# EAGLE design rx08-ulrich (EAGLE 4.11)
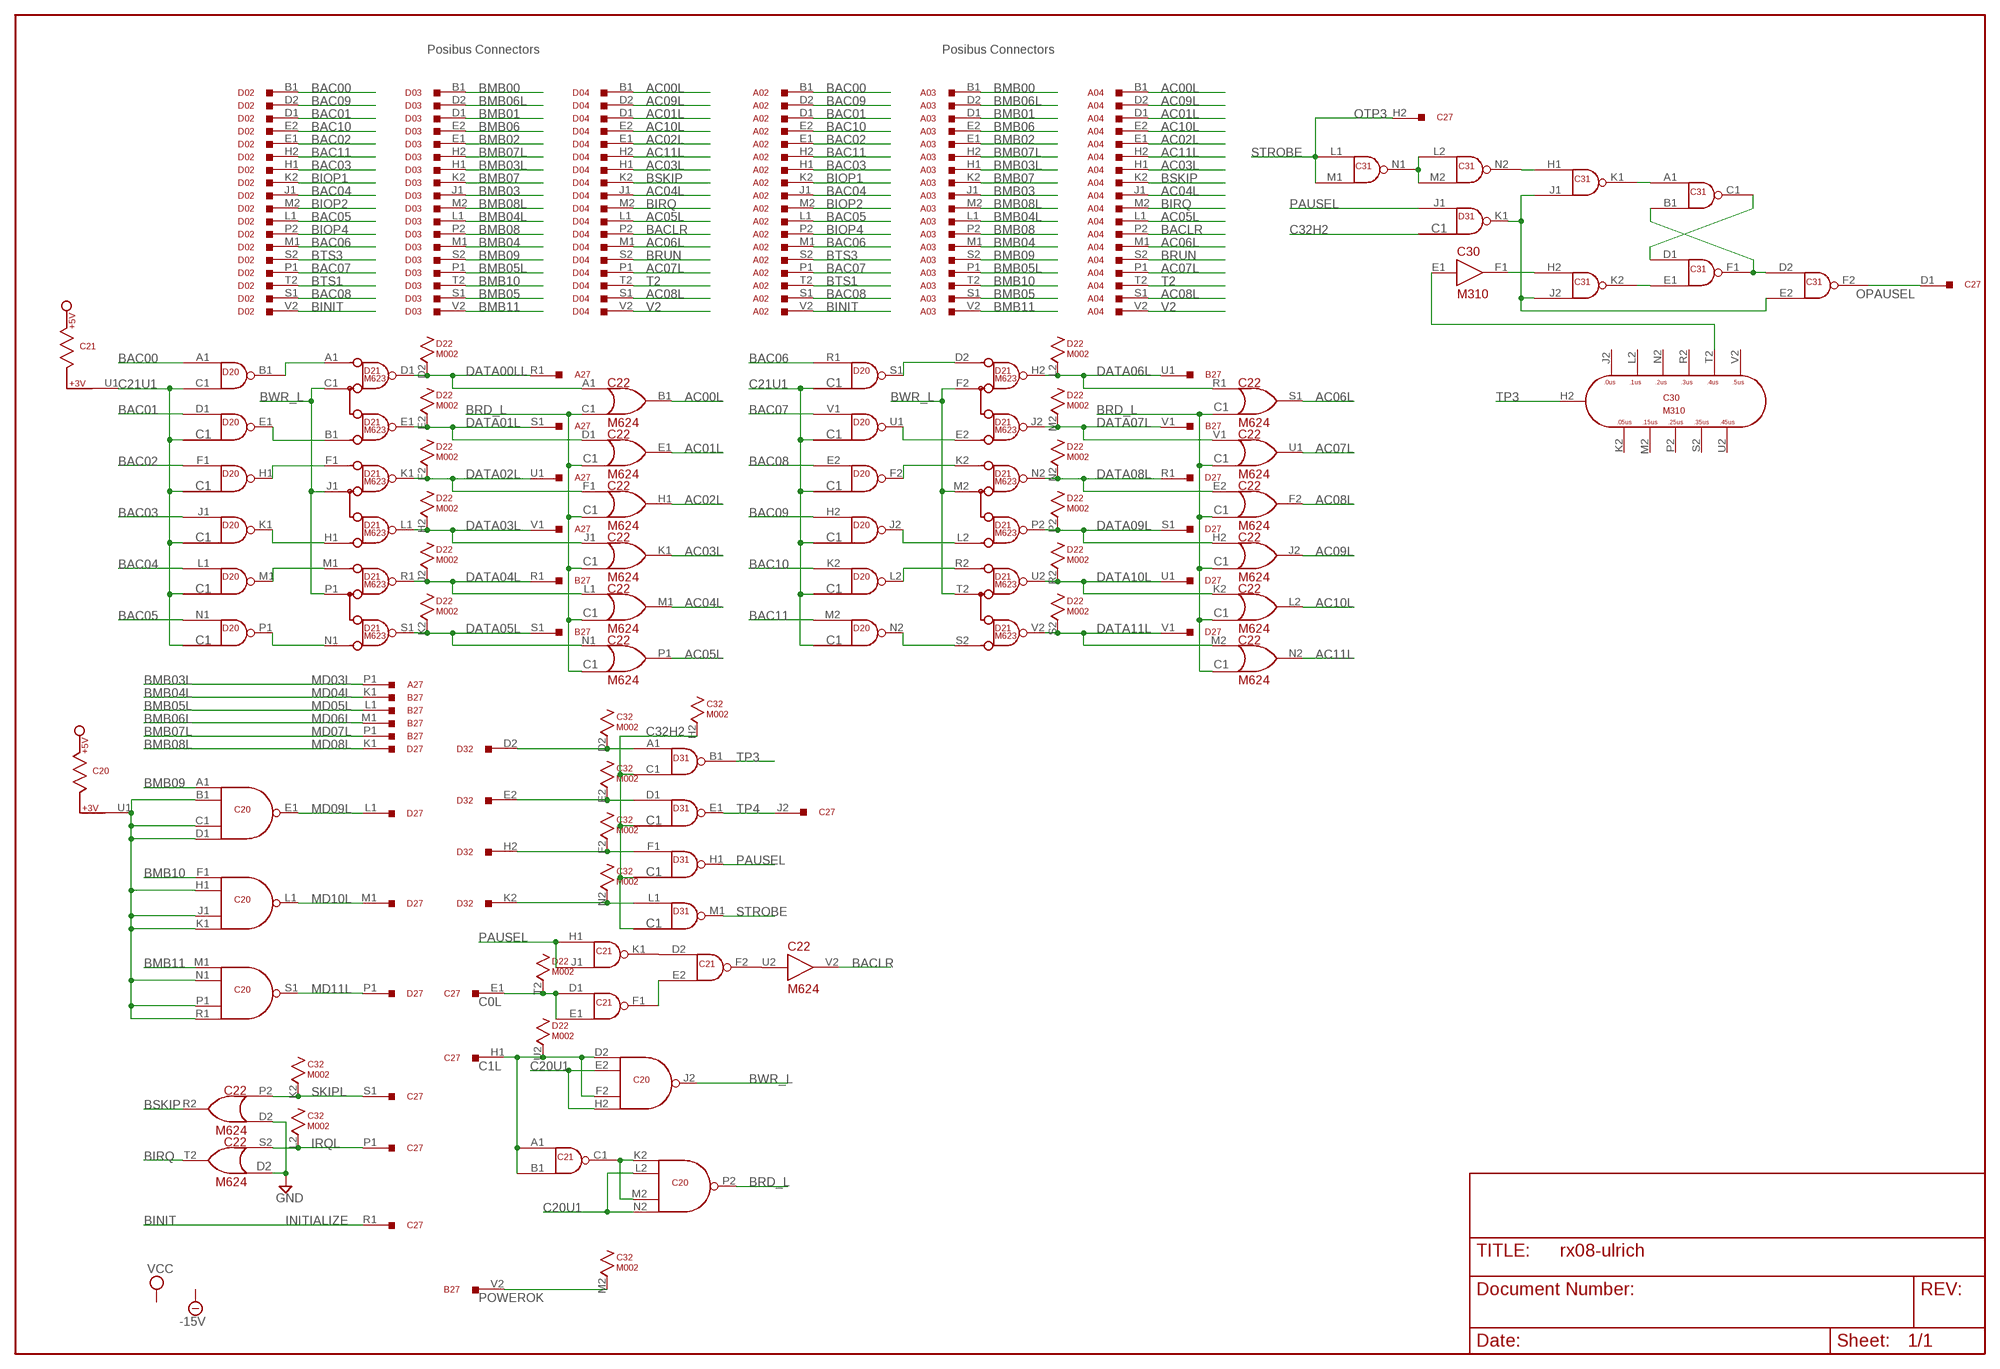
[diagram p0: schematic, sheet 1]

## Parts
A02  M903  [H807]
A03  M903  [H807]
A04  M903  [H807]
A27  M916  [H807]
B27  M916  [H807]
C20  M617  [H807]
C21  M113  [H807]
C22  M624  [H807]
C27  M916  [H807]
C30  M310  [H807]
C31  M113  [H807]
C32  M002  [H807]
D02  M903  [H807]
D03  M903  [H807]
D04  M903  [H807]
D20  M101  [H807]
D21  M623  [H807]
D22  M002  [H807]
D27  M916  [H807]
D31  M101  [H807]
D32  M903  [H807]

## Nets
AC00L: A04.B1 C22.B1(OUT) D04.B1
AC01L: A04.D1 C22.E1(OUT) D04.D1
AC02L: A04.E1 C22.H1(OUT) D04.E1
AC03L: A04.H1 C22.K1(OUT) D04.H1
AC04L: A04.J1 C22.M1(OUT) D04.J1
AC05L: A04.L1 C22.P1(OUT) D04.L1
AC06L: A04.M1 C22.S1(OUT) D04.M1
AC07L: A04.P1 C22.U1(OUT) D04.P1
AC08L: A04.S1 C22.F2(OUT) D04.S1
AC09L: A04.D2 C22.J2(OUT) D04.D2
AC10L: A04.E2 C22.L2(OUT) D04.E2
AC11L: A04.H2 C22.N2(OUT) D04.H2
BAC00: A02.B1 D02.B1 D20.A1(IN1)
BAC01: A02.D1 D02.D1 D20.D1(IN)
BAC02: A02.E1 D02.E1 D20.F1(IN)
BAC03: A02.H1 D02.H1 D20.J1(IN)
BAC04: A02.J1 D02.J1 D20.L1(IN)
BAC05: A02.L1 D02.L1 D20.N1(IN)
BAC06: A02.M1 D02.M1 D20.R1(IN)
BAC07: A02.P1 D02.P1 D20.V1(IN)
BAC08: A02.S1 D02.S1 D20.E2(IN)
BAC09: A02.D2 D02.D2 D20.H2(IN)
BAC10: A02.E2 D02.E2 D20.K2(IN)
BAC11: A02.H2 D02.H2 D20.M2(IN)
BACLR: A04.P2 C22.V2(OUT) D04.P2
BINIT: A02.V2 C27.R1 D02.V2
BIOP1: A02.K2 D02.K2
BIOP2: A02.M2 D02.M2
BIOP4: A02.P2 D02.P2
BIRQ: A04.M2 C22.T2(OUT) D04.M2
BMB00: A03.B1 D03.B1
BMB01: A03.D1 D03.D1
BMB02: A03.E1 D03.E1
BMB03: A03.J1 D03.J1
BMB03L: A03.H1 A27.P1 D03.H1
BMB04: A03.M1 D03.M1
BMB04L: A03.L1 B27.K1 D03.L1
BMB05: A03.S1 D03.S1
BMB05L: A03.P1 B27.L1 D03.P1
BMB06: A03.E2 D03.E2
BMB06L: A03.D2 B27.M1 D03.D2
BMB07: A03.K2 D03.K2
BMB07L: A03.H2 B27.P1 D03.H2
BMB08: A03.P2 D03.P2
BMB08L: A03.M2 D03.M2 D27.K1
BMB09: A03.S2 C20.A1(IN1) D03.S2
BMB10: A03.T2 C20.F1(IN1) D03.T2
BMB11: A03.V2 C20.M1(IN1) D03.V2
BRD_L: C20.P2(OUT) C22.C1(IN2)
BRUN: A04.S2 D04.S2
BSKIP: A04.K2 C22.R2(OUT) D04.K2
BTS1: A02.T2 D02.T2
BTS3: A02.S2 D02.S2
BWR_L: C20.J2(OUT) D21.C1(C) D21.F2(C) D21.J1(C) D21.M2(C) D21.P1(C) D21.T2(C)
C0L: C21.D1(IN1) C21.E1(IN2) C27.E1 D22.T2
C1L: C20.D2(IN1) C20.F2(IN3) C21.A1(IN1) C21.B1(IN2) C27.H1 D22.U2
C20U1: C20.B1(IN2) C20.C1(IN3) C20.D1(IN4) C20.E2(IN2) C20.H1(IN2) C20.H2(IN4) C20.J1(IN3) C20.K1(IN4) C20.L2(IN2) C20.N1(IN2) C20.N2(IN4) C20.P1(IN3) C20.R1(IN4) C20.U1
C21U1: C21.U1 D20.C1(IN2)
C32H2: C32.H2 D31.C1(IN2)
DATA00LL: A27.R1 C22.A1(IN1) D21.D1(D) D22.D2
DATA01L: A27.S1 C22.D1(IN) D21.E1(E) D22.E2
DATA02L: A27.U1 C22.F1(IN) D21.K1(D) D22.F2
DATA03L: A27.V1 C22.J1(IN) D21.L1(E) D22.H2
DATA04L: B27.R1 C22.L1(IN) D21.R1(D) D22.J2
DATA05L: B27.S1 C22.N1(IN) D21.S1(E) D22.K2
DATA06L: B27.U1 C22.R1(IN) D21.H2(D) D22.L2
DATA07L: B27.V1 C22.V1(IN) D21.J2(E) D22.M2
DATA08L: C22.E2(IN) D21.N2(D) D22.N2 D27.R1
DATA09L: C22.H2(IN) D21.P2(E) D22.P2 D27.S1
DATA10L: C22.K2(IN) D21.U2(D) D22.R2 D27.U1
DATA11L: C22.M2(IN) D21.V2(E) D22.S2 D27.V1
GND: C22.D2(IN2)
IRQL: C22.S2(IN) C27.P1 C32.L2
MD09L: C20.E1(OUT) D27.L1
MD10L: C20.L1(OUT) D27.M1
MD11L: C20.S1(OUT) D27.P1
N$1: D20.B1(OUT) D21.A1(A)
N$2: D20.E1(OUT) D21.B1(B)
N$3: D20.H1(OUT) D21.F1(A)
N$4: D20.K1(OUT) D21.H1(B)
N$5: D20.P1(OUT) D21.N1(B)
N$6: D20.M1(OUT) D21.M1(A)
N$7: C20.K2(IN1) C20.M2(IN3) C21.C1(OUT)
N$8: D20.N2(OUT) D21.S2(B)
N$9: C32.D2 D31.A1(IN1) D32.D2
N$10: D20.J2(OUT) D21.L2(B)
N$11: D20.U1(OUT) D21.E2(B)
N$12: D20.S1(OUT) D21.D2(A)
N$13: D20.F2(OUT) D21.K2(A)
N$14: D20.L2(OUT) D21.R2(A)
N$15: C32.E2 D31.D1(IN) D32.E2
N$16: C32.F2 D31.F1(IN) D32.H2
N$17: C32.N2 D31.L1(IN) D32.K2
N$18: C31.E2(IN2) C31.J1(IN2) C31.J2(IN2) D31.K1(OUT)
N$19: C21.E2(IN2) C21.F1(OUT)
N$20: C21.D2(IN1) C21.K1(OUT)
N$21: C31.C1(OUT) C31.D1(IN1)
N$22: C31.B1(IN2) C31.D2(IN1) C31.F1(OUT)
N$23: C21.F2(OUT) C22.U2(IN)
N$24: C30.E1(IN) C30.T2
N$25: C30.F1(OUT) C31.H2(IN1)
N$26: C31.L2(IN1) C31.M2(IN2) C31.N1(OUT)
N$28: C31.H1(IN1) C31.N2(OUT)
N$29: C31.A1(IN1) C31.K1(OUT)
N$30: C31.E1(IN2) C31.K2(OUT)
OPAUSEL: C27.D1 C31.F2(OUT)
PAUSEL: C21.H1(IN1) C21.J1(IN2) D31.H1(OUT) D31.J1(IN)
POWEROK: B27.V2 C32.M2
SKIPL: C22.P2(IN1) C27.S1 C32.K2
STROBE: C27.H2 C31.L1(IN1) C31.M1(IN2) D31.M1(OUT)
T2: A04.T2 D04.T2
TP3: C30.H2 D31.B1(OUT)
TP4: C27.J2 D31.E1(OUT)
V2: A04.V2 D04.V2
Unconnected: A27.A1 A27.A2 A27.B1 A27.B2 A27.C1 A27.C2 A27.D1 A27.D2 A27.E1 A27.E2 A27.F1 A27.F2 A27.H1 A27.H2 A27.J1 A27.J2 A27.K1 A27.K2 A27.L1 A27.L2 A27.M1 A27.M2 A27.N1 A27.N2 A27.P2 A27.R2 A27.S2 A27.T1 A27.T2 A27.U2 A27.V2 B27.A1 B27.A2 B27.B1 B27.B2 B27.C1 B27.C2 B27.D1 B27.D2 B27.E1 B27.E2 B27.F1 B27.F2 B27.H1 B27.H2 B27.J1 B27.J2 B27.K2 B27.L2 B27.M2 B27.N1 B27.N2 B27.P2 B27.R2 B27.S2 B27.T1 B27.T2 B27.U2 C20.R2(IN1) C20.S2(IN2) C20.T2(IN3) C20.U2(IN4) C20.V1 C20.V2(OUT) C21.H2(IN1) C21.J2(IN2) C21.K2(OUT) C21.L1(IN1) C21.L2(IN1) C21.M1(IN2) C21.M2(IN2) C21.N1(OUT) C21.N2(OUT) C21.P1(IN1) C21.P2(IN1) C21.R1(IN2) C21.R2(IN2) C21.S1(OUT) C21.S2(OUT) C21.T2(IN1) C21.U2(IN2) C21.V1 C21.V2(OUT) C27.A1 C27.A2 C27.B1 C27.B2 C27.C1 C27.C2 C27.D2 C27.E2 C27.F1 C27.F2 C27.J1 C27.K1 C27.K2 C27.L1 C27.L2 C27.M1 C27.M2 C27.N1 C27.N2 C27.P2 C27.R2 C27.S2 C27.T1 C27.T2 C27.U1 C27.U2 C27.V1 C27.V2 C30.H1(IN) C30.J1(OUT) C30.J2 C30.K2 C30.L2 C30.M2 C30.N2 C30.P2 C30.R2 C30.S2 C30.U2 C30.V2 C31.P1(IN1) C31.P2(IN1) C31.R1(IN2) C31.R2(IN2) C31.S1(OUT) C31.S2(OUT) C31.T2(IN1) C31.U1 C31.U2(IN2) C31.V1 C31.V2(OUT) C32.J2 C32.P2 C32.R2 C32.S2 C32.T2 C32.U2 C32.V2 D20.P2(IN) D20.R2(OUT) D20.S2(IN) D20.T2(OUT) D20.U2(IN) D20.V2(OUT) D22.V2 D27.A1 D27.A2 D27.B1 D27.B2 D27.C1 D27.C2 D27.D1 D27.D2 D27.E1 D27.E2 D27.F1 D27.F2 D27.H1 D27.H2 D27.J1 D27.J2 D27.K2 D27.L2 D27.M2 D27.N1 D27.N2 D27.P2 D27.R2 D27.S2 D27.T1 D27.T2 D27.U2 D27.V2 D31.E2(IN) D31.F2(OUT) D31.H2(IN) D31.J2(OUT) D31.K2(IN) D31.L2(OUT) D31.M2(IN) D31.N1(IN) D31.N2(OUT) D31.P1(OUT) D31.P2(IN) D31.R1(IN) D31.R2(OUT) D31.S1(OUT) D31.S2(IN) D31.T2(OUT) D31.U1(OUT) D31.U2(IN) D31.V1(IN) D31.V2(OUT) D32.B1 D32.D1 D32.E1 D32.H1 D32.J1 D32.L1 D32.M1 D32.M2 D32.P1 D32.P2 D32.S1 D32.S2 D32.T2 D32.V2

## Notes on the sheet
- Posibus Connectors | Posibus Connectors
- OTP3
- MD03L
- MD04L
- MD05L
- MD06L
- MD07L
- MD08L
- INITIALIZE

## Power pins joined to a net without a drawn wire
-15V: C32.B2(-15V) D22.B2(-15V)
GND: A02.A1 A02.C1 A02.C2 A02.F1 A02.F2 A02.J2 A02.K1 A02.L2 A02.N1 A02.N2 A02.R1 A02.R2 A02.T1 A02.U2 A03.A1 A03.C1 A03.C2 A03.F1 A03.F2 A03.J2 A03.K1 A03.L2 A03.N1 A03.N2 A03.R1 A03.R2 A03.T1 A03.U2 A04.A1 A04.C1 A04.C2 A04.F1 A04.F2 A04.J2 A04.K1 A04.L2 A04.N1 A04.N2 A04.R1 A04.R2 A04.T1 A04.U2 C20.C2(GND) C20.T1(GND) C21.C2(GND) C21.T1(GND) C22.C2(GND) C22.T1(GND) C30.C2(GND) C30.T1(GND) C31.C2(GND) C31.T1(GND) C32.C2(GND) D02.A1 D02.C1 D02.C2 D02.F1 D02.F2 D02.J2 D02.K1 D02.L2 D02.N1 D02.N2 D02.R1 D02.R2 D02.T1 D02.U2 D03.A1 D03.C1 D03.C2 D03.F1 D03.F2 D03.J2 D03.K1 D03.L2 D03.N1 D03.N2 D03.R1 D03.R2 D03.T1 D03.U2 D04.A1 D04.C1 D04.C2 D04.F1 D04.F2 D04.J2 D04.K1 D04.L2 D04.N1 D04.N2 D04.R1 D04.R2 D04.T1 D04.U2 D20.C2(GND) D20.T1(GND) D21.C2(GND) D21.T1(GND) D21.U1(GND) D21.V1(GND) D22.C2(GND) D31.C2(GND) D31.T1(GND) D32.A1 D32.C1 D32.C2 D32.F1 D32.F2 D32.J2 D32.K1 D32.L2 D32.N1 D32.N2 D32.R1 D32.R2 D32.T1 D32.U2
VCC: C20.A2(VCC) C21.A2(VCC) C22.A2(VCC) C30.A2(VCC) C31.A2(VCC) C32.A2(VCC) D20.A2(VCC) D21.A2(VCC) D22.A2(VCC) D31.A2(VCC)

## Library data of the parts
A02-A04 D02-D04 D32 = dec-m:M903: Two-sided Posibus cable/connector.
A27 B27 C27 D27 = dec-m:M916: Simple 36 pin connector/wire cable
C20 = dec-m:M617: 6 4-input NAND Buffers
C21 C31 = dec-m:M113: 10 2-input NAND Gates
C22 = dec-m:M624: Bus Data Interface The M101 contains 15 two-input NAND gates. One input of each gate is tied to a common line so that all data signals can be enabled simultaneously. Each data signal presents one TTL load. The common input presents 15 loads. Each output can drive 10 loads. Power: 5V@82ma (max.)
C30 = dec-m:M310: Tapped Delay Line
C32 D22 = dec-m:M002: 15 Clamped Loads
D20 D31 = dec-m:M101: Bus Data Interface The M101 contains 15 two-input NAND gates. One input of each gate is tied to a common line so that all data signals can be enabled simultaneously. Each data signal presents one TTL load. The common input presents 15 loads. Each output can drive 10 loads. Power: 5V@82ma (max.)
D21 = dec-m:M623: 6 Dual Bus Drivers

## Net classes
1 Supply: width 1.905 mm, drill 0.508 mm

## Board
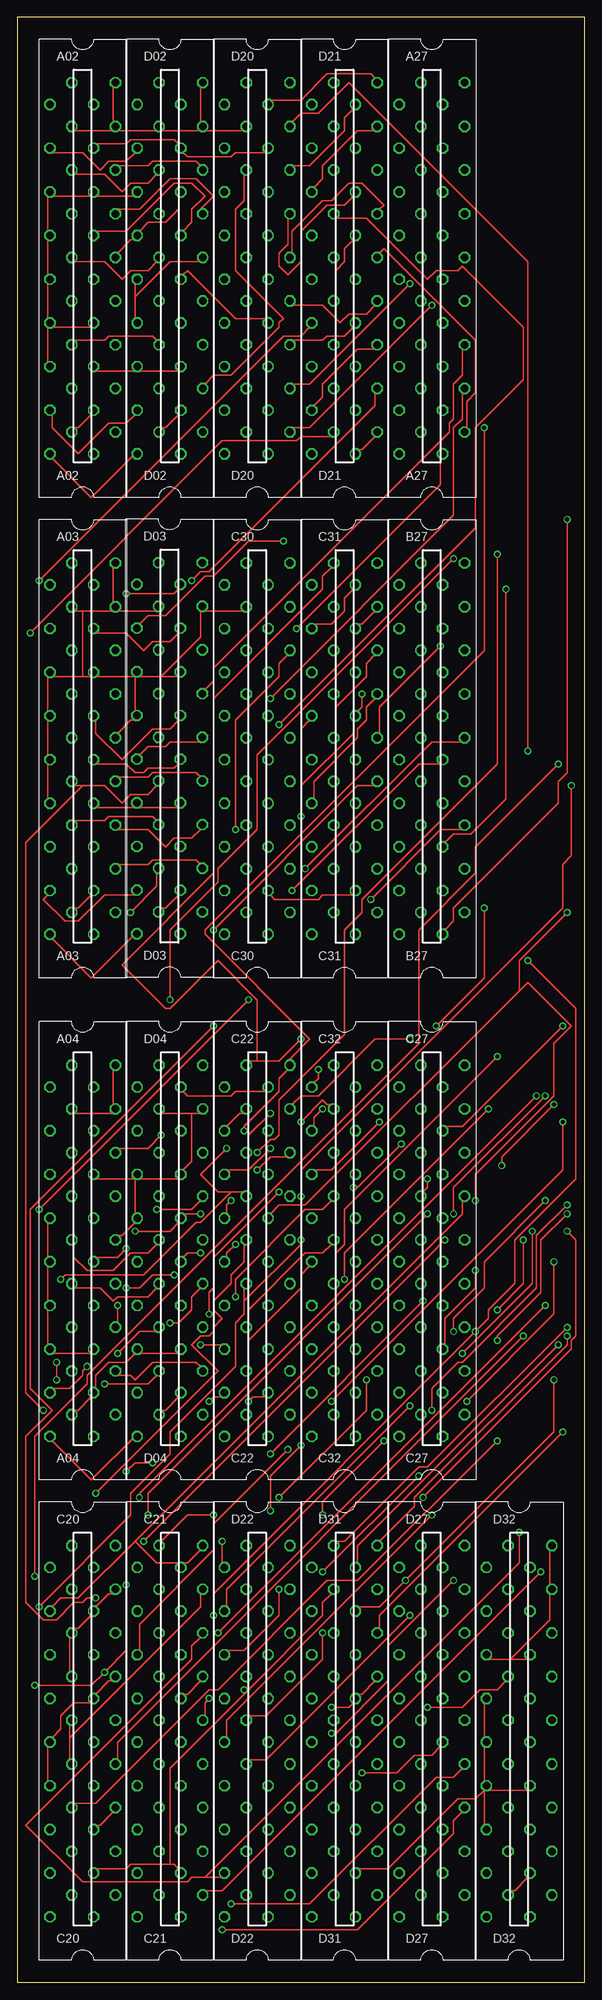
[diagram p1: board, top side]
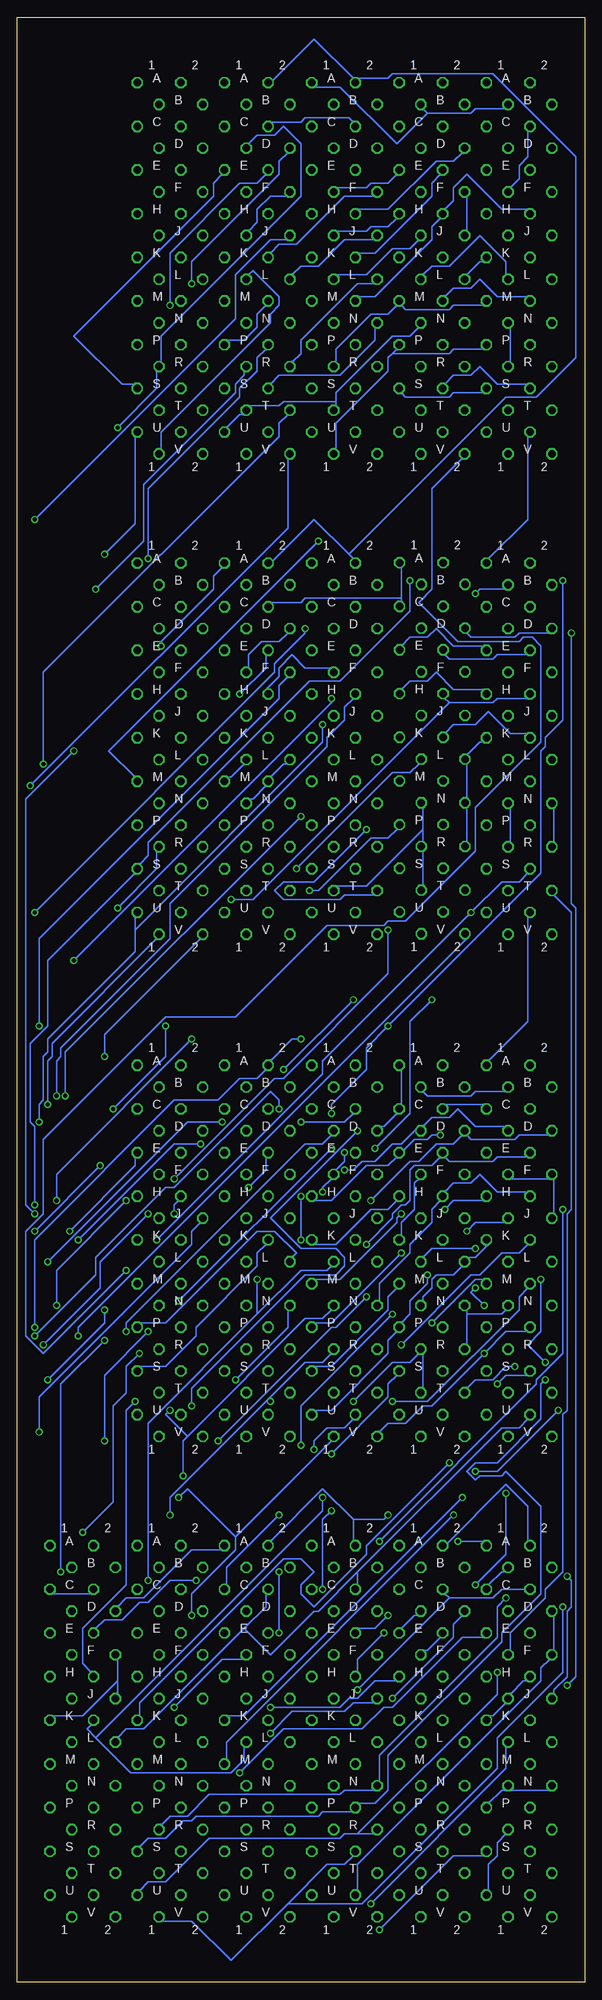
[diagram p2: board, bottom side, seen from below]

Size 82.55 x 285.75 mm. Coordinates in mm from the lower left corner, seen from the top.
Outline: 0,0 82.55,0 82.55,285.75 0,285.75 0,0
Copper layers (1*16): Top 0.035mm / dielectric 1.5mm / Bottom 0.035mm
Design rules "olimex10mil": minimum track width 10mil, minimum drill 24mil, track to track 10mil, track to pad 10mil, pad to pad 10mil, via to via 10mil, smd to smd 10mil, copper to edge 40mil, drill to drill 10mil, minimum pad ring 10mil, minimum via ring 8mil, stop-mask expansion 0mil, vias tented up to drill 0mil, thermal gap 10mil

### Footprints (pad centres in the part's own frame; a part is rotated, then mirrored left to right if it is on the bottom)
H807 = drill 1.092 octagon: A1 4.763,28.575; A2 -1.587,28.575; B1 1.587,25.4; B2 -4.763,25.4; C1 4.763,22.225; C2 -1.587,22.225; D1 1.587,19.05; D2 -4.763,19.05; E1 4.763,15.875; E2 -1.587,15.875; F1 1.587,12.7; F2 -4.763,12.7; H1 4.763,9.525; H2 -1.587,9.525; J1 1.587,6.35; J2 -4.763,6.35; K1 4.763,3.175; K2 -1.587,3.175; L1 1.587,0; L2 -4.763,0; M1 4.763,-3.175; M2 -1.587,-3.175; N1 1.587,-6.35; N2 -4.763,-6.35; P1 4.763,-9.525; P2 -1.587,-9.525; R1 1.587,-12.7; R2 -4.763,-12.7; S1 4.763,-15.875; S2 -1.587,-15.875; T1 1.587,-19.05; T2 -4.763,-19.05; U1 4.763,-22.225; U2 -1.587,-22.225; V1 1.587,-25.4; V2 -4.763,-25.4

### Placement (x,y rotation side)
A02  9.53,247.65 0 top
A03  9.53,177.8 0 top
A04  9.53,104.78 0 top
A27  60.33,247.65 0 top
B27  60.33,177.8 0 top
C20  9.53,34.92 0 top
C21  22.23,34.92 0 top
C22  34.92,104.78 0 top
C27  60.33,104.78 0 top
C30  34.92,177.8 0 top
C31  47.62,177.8 0 top
C32  47.62,104.78 0 top
D02  22.23,247.65 0 top
D03  22.16,177.86 0 top
D04  22.23,104.78 0 top
D20  34.92,247.65 0 top
D21  47.62,247.65 0 top
D22  34.92,34.92 0 top
D27  60.33,34.92 0 top
D31  47.62,34.92 0 top
D32  73.03,34.92 0 top

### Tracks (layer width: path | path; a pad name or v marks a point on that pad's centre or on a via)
-15V  (via drill 0.61)
  Top 0.254: v29.84,64.14 29.84,60.96 D22.B2 | v3.17,112.39 v33.66,142.88 | v43.81,132.72 43.81,131.44 43.18,130.81 C32.B2
  Bottom 0.254: v29.84,64.14 6.99,87 6.99,87.63 3.17,91.44 v3.17,112.39 | v33.66,142.88 v43.81,132.72
AC00L
  Top 0.254: C22.B1 36.2,129.54 31.75,129.54 31.11,128.91 24.77,128.91 24.13,129.54 D04.B1
  Bottom 0.254: A04.B1 11.43,129.54 15.88,129.54 16.51,128.91 22.86,128.91 23.5,129.54 D04.B1
AC01L  (via drill 0.61)
  Top 0.254: v34.92,118.11 36.83,120.02 39.37,120.02 C22.E1
  Bottom 0.254: A04.D1 11.43,124.46 15.88,124.46 18.41,127 19.68,125.73 22.23,125.73 23.5,124.46 D04.D1 24.13,124.46 26.67,121.92 27.94,121.92 30.48,119.38 32.38,119.38 33.66,118.11 v34.92,118.11
AC02L  (via drill 0.61)
  Top 0.254: v20.95,123.19 19.05,121.28 14.61,121.28 A04.E1
  Bottom 0.254: v20.95,123.19 22.23,123.19 22.86,122.56 24.77,122.56 26.67,120.65 D04.E1 27.3,120.02 28.57,118.75 31.75,118.75 36.83,113.67 39.37,113.67 C22.H1
AC03L  (via drill 0.61)
  Top 0.254: v20.32,112.39 25.4,112.39 26.67,113.67 D04.H1
  Bottom 0.254: v20.32,112.39 19.05,113.67 14.61,113.67 A04.H1 | C22.K1 39.37,107.31 36.2,107.31 31.11,112.39 28.57,112.39 27.3,113.67 D04.H1
AC04L  (via drill 0.61)
  Top 0.254: v17.14,109.22 22.23,109.22 23.5,110.49 D04.J1 24.13,111.76 v26.67,111.76
  Bottom 0.254: v17.14,109.22 15.88,110.49 11.43,110.49 A04.J1 | v26.67,111.76 27.3,111.12 27.3,110.49 35.56,102.23 39.37,102.23 C22.M1
AC05L  (via drill 0.61)
  Top 0.254: v15.88,106.68 14.61,105.41 11.43,105.41 A04.L1 | v26.67,106.05 24.77,106.05 24.13,105.41 D04.L1
  Bottom 0.254: v15.88,106.68 22.23,106.68 23.5,105.41 D04.L1 | v26.67,106.05 36.83,95.89 39.37,95.89 C22.P1
AC06L  (via drill 0.61)
  Top 0.254: v22.23,95.89 23.5,95.89 25.4,97.79 25.4,99.69 26.67,100.97 D04.M1
  Bottom 0.254: v22.23,95.89 15.88,102.23 14.61,102.23 A04.M1 | C22.S1 39.37,89.53 36.83,89.53 28.57,97.79 28.57,99.69 27.3,100.97 D04.M1
AC07L  (via drill 0.61)
  Top 0.254: v14.61,98.42 14.61,95.89 A04.P1 | v15.88,100.97 17.78,100.97 19.68,102.87 v22.86,102.87
  Bottom 0.254: v14.61,98.42 16.51,100.33 v15.88,100.97 | v22.86,102.87 22.86,101.6 25.4,99.06 25.4,97.16 26.67,95.89 D04.P1 27.3,94.61 28.57,93.34 28.57,91.44 36.83,83.19 39.37,83.19 C22.U1
AC08L  (via drill 0.61)
  Top 0.254: A04.S1 14.61,88.27 16.51,88.27 17.14,87.63 19.68,90.17 26.04,90.17 26.67,89.53 D04.S1 | v36.83,121.28 33.66,118.11 30.48,118.11 C22.F2 | v36.83,76.83 v59.05,99.06
  Bottom 0.254: v59.05,99.06 v36.83,121.28 | v36.83,76.83 28.57,85.09 28.57,87 27.3,88.27 D04.S1
AC09L  (via drill 0.61)
  Top 0.254: v31.11,113.67 30.48,113.03 30.48,111.76 C22.J2
  Bottom 0.254: A04.D2 5.08,123.19 9.53,123.19 10.16,122.56 16.51,122.56 17.14,123.19 D04.D2 17.78,123.19 19.05,121.92 21.59,121.92 24.13,119.38 25.4,119.38 v31.11,113.67
AC10L  (via drill 0.61)
  Top 0.254: v31.75,107.31 30.48,106.05 30.48,105.41 C22.L2
  Bottom 0.254: A04.E2 8.26,120.02 12.7,120.02 13.34,119.38 19.68,119.38 20.32,120.02 D04.E2 20.95,120.02 22.23,118.75 24.77,118.75 25.4,118.11 25.4,113.67 26.04,113.03 26.67,113.03 27.94,111.76 27.94,111.12 v31.75,107.31
AC11L
  Bottom 0.254: A04.H2 8.26,114.94 12.7,114.94 15.24,117.47 16.51,116.2 19.05,116.2 20.32,114.94 D04.H2 20.95,113.67 22.23,112.39 22.23,110.49 25.4,107.31 25.4,106.05 29.84,101.6 29.84,99.06 C22.N2
BAC00
  Bottom 0.254: 22.86,271.78 16.51,271.78 15.88,272.42 11.43,272.42 A02.B1 | 22.86,271.78 23.5,272.42 D02.B1 | 22.86,271.78 27.3,267.33 35.56,275.59 39.37,275.59 D20.A1
BAC01
  Top 0.254: A02.D1 11.43,267.33 15.88,267.33 16.51,267.97 22.86,267.97 23.5,267.33 D02.D1 24.13,266.06 24.77,265.43 31.11,265.43 31.75,266.06 36.2,266.06 D20.D1
BAC02
  Top 0.254: A02.E1 14.61,264.16 19.05,264.16 19.68,264.8 26.04,264.8 26.67,264.16 D02.E1
  Bottom 0.254: D20.F1 36.2,260.99 31.75,260.99 31.11,261.62 28.57,261.62 27.3,262.89 D02.E1
BAC03
  Top 0.254: A02.H1 14.61,257.81 17.78,257.81 22.23,262.25 26.04,262.25 28.57,259.71 26.67,257.81 D02.H1
  Bottom 0.254: D20.J1 36.2,254.63 31.75,254.63 31.11,255.27 28.57,255.27 27.3,256.54 D02.H1
BAC04
  Top 0.254: A02.J1 11.43,254.63 15.88,254.63 22.86,261.62 25.4,261.62 27.3,259.71 25.4,257.81 25.4,255.91 24.13,254.63 D02.J1
  Bottom 0.254: D20.L1 36.2,248.28 31.75,248.28 27.94,252.09 25.4,252.09 24.13,253.37 D02.J1
BAC05
  Top 0.254: D20.N1 36.2,241.94 31.75,241.94 24.77,248.92 24.13,248.28 D02.L1
  Bottom 0.254: A02.L1 11.43,248.28 11.43,250.19 15.24,254 19.68,249.56 22.23,249.56 23.5,248.28 D02.L1
BAC06
  Bottom 0.254: A02.M1 14.61,243.84 19.05,243.84 19.68,243.21 26.04,243.21 26.67,243.84 D02.M1 27.3,243.84 28.57,242.57 31.11,242.57 36.2,237.49 36.2,235.59 D20.R1
BAC07
  Bottom 0.254: 27.94,236.85 27.3,237.49 D02.P1 | 27.94,236.85 28.57,236.22 28.57,234.31 36.2,226.69 36.2,222.88 D20.V1 | 27.94,236.85 19.68,236.85 19.05,237.49 14.61,237.49 A02.P1
BAC08
  Top 0.254: D20.E2 33.02,262.89 33.02,259.08 31.75,257.81 31.75,248.92 38.73,241.94 38.1,241.3 38.1,240.66 31.11,233.68 28.57,233.68 27.3,232.41 D02.S1
  Bottom 0.254: A02.S1 14.61,231.14 19.05,231.14 19.68,230.5 26.04,230.5 26.67,231.14 D02.S1
BAC09
  Top 0.254: A02.D2 5.08,266.06 9.53,266.06 12.06,263.52 13.34,264.8 15.88,264.8 17.14,266.06 D02.D2
  Bottom 0.254: D20.H2 33.02,257.81 28.57,257.81 21.59,264.8 19.05,264.8 17.78,266.06 D02.D2
BAC10
  Top 0.254: A02.E2 8.26,262.89 12.7,262.89 15.24,260.35 16.51,261.62 19.05,261.62 20.32,262.89 D02.E2
  Bottom 0.254: D20.K2 33.02,251.46 30.48,251.46 22.23,259.71 22.23,261.62 20.95,262.89 D02.E2
BAC11
  Bottom 0.254: A02.H2 8.26,257.81 12.06,257.81 17.14,262.89 19.05,260.99 19.05,259.08 20.32,257.81 D02.H2 20.95,256.54 22.23,255.27 22.23,253.37 30.48,245.11 33.02,245.11 D20.M2
BACLR  (via drill 0.61)
  Top 0.254: v14.61,91.44 17.78,94.61 20.32,94.61 D04.P2
  Bottom 0.254: A04.P2 8.26,94.61 11.43,94.61 v14.61,91.44 22.23,83.82 23.5,83.82 26.04,81.28 28.57,81.28 29.84,80.01 C22.V2
BINIT  (via drill 0.61)
  Top 0.254: v66.67,103.5 66.67,100.97 62.23,96.52 62.23,92.71 C27.R1 | A02.V2 5.08,221.62 10.79,215.9 17.14,222.25 D02.V2
  Bottom 0.254: v66.67,103.5 78.74,91.44 81.28,93.98 81.28,109.22 78.74,111.76 78.74,122.56 60.96,140.34 50.8,140.34 37.47,153.67 29.21,153.67 28.57,154.31 26.04,154.31 15.88,164.47 15.88,170.81 6.35,180.34 6.35,194.31 7.62,195.58 8.89,195.58 9.53,194.94 18.41,194.94 24.13,200.66 22.23,202.56 22.23,217.17 17.78,221.62 D02.V2
BIOP1
  Top 0.254: A02.K2 8.26,250.19 12.7,250.19 15.24,247.65 16.51,248.92 19.05,248.92 20.32,250.19 D02.K2
BIOP2
  Bottom 0.254: A02.M2 8.26,245.11 12.7,245.11 15.24,247.65 16.51,246.38 19.05,246.38 20.32,245.11 D02.M2
BIOP4
  Top 0.254: A02.P2 8.26,238.76 12.7,238.76 13.34,239.4 19.68,239.4 20.32,238.76 D02.P2
BIRQ  (via drill 0.61)
  Top 0.254: A04.M2 8.26,100.97 12.06,100.97 13.97,99.06 14.61,99.69 19.05,99.69 20.32,100.97 D04.M2 | v27.94,84.45 28.57,85.09 29.84,85.09 C22.T2
  Bottom 0.254: v27.94,84.45 22.86,84.45 9.53,97.79 9.53,99.69 8.26,100.97 A04.M2
BMB00  (via drill 0.61)
  Top 0.254: v15.88,201.93 22.86,201.93 23.5,202.56 D03.B1
  Bottom 0.254: v15.88,201.93 15.24,202.56 11.43,202.56 A03.B1
BMB01
  Top 0.254: A03.D1 11.43,196.22 15.88,196.22 18.41,193.68 19.68,194.94 22.23,194.94 23.5,196.22 D03.D1
BMB02
  Bottom 0.254: A03.E1 14.61,194.31 19.05,194.31 21.59,196.85 22.86,195.58 25.4,195.58 26.67,194.31 D03.E1
BMB03
  Top 0.254: A03.J1 11.43,183.51 11.43,181.61 15.24,177.8 19.68,182.25 22.23,182.25 23.5,183.51 D03.J1
BMB03L
  Top 0.254: A27.P1 64.77,237.49 64.77,233.68 63.5,232.41 63.5,227.33 62.87,226.69 62.87,225.43 28.57,191.13 28.57,189.23 27.3,187.96 D03.H1
  Bottom 0.254: A03.H1 14.61,187.96 19.05,187.96 21.59,190.5 22.86,189.23 25.4,189.23 26.67,187.96 D03.H1
BMB04
  Top 0.254: A03.M1 14.61,175.26 19.05,175.26 19.68,175.9 26.04,175.9 26.67,175.26 D03.M1
BMB04L  (via drill 0.61)
  Top 0.254: A03.L1 11.43,177.16 15.88,177.16 17.14,175.9 18.41,175.9 19.05,176.53 22.86,176.53 23.5,177.16 D03.L1 | v41.91,161.93 60.33,180.34 64.77,180.34 B27.K1
  Bottom 0.254: v41.91,161.93 27.94,175.9 25.4,175.9 24.13,177.16 D03.L1
BMB05
  Top 0.254: A03.S1 14.61,162.56 19.05,162.56 19.68,163.19 26.04,163.19 26.67,162.56 D03.S1
BMB05L  (via drill 0.61)
  Top 0.254: A03.P1 14.61,167.64 19.05,167.64 21.59,165.1 22.86,166.37 25.4,166.37 26.67,167.64 D03.P1 | v40.01,158.75 58.42,177.16 61.59,177.16 B27.L1
  Bottom 0.254: v40.01,158.75 38.73,158.75 31.11,166.37 28.57,166.37 27.3,167.64 D03.P1
BMB06
  Bottom 0.254: A03.E2 8.26,193.04 12.7,193.04 13.34,192.41 19.68,192.41 20.32,193.04 D03.E2
BMB06L  (via drill 0.61)
  Top 0.254: v38.73,209.55 33.66,209.55 28.57,204.47 27.3,204.47 21.59,198.75 19.05,198.75 17.78,197.49 D03.D2
  Bottom 0.254: A03.D2 5.08,196.22 9.53,196.22 10.16,195.58 16.51,195.58 17.14,196.22 D03.D2 | v38.73,209.55 69.22,179.07 65.41,175.26 B27.M1
BMB07
  Bottom 0.254: A03.K2 8.26,181.61 10.79,181.61 13.97,184.78 15.88,182.88 19.05,182.88 20.32,181.61 D03.K2
BMB07L  (via drill 0.61)
  Top 0.254: v51.44,157.48 61.59,167.64 64.77,167.64 B27.P1
  Bottom 0.254: 19.68,186.06 13.34,186.06 12.7,186.69 8.26,186.69 A03.H2 | 19.68,186.06 20.32,186.69 D03.H2 | v51.44,157.48 48.26,157.48 19.68,186.06
BMB08
  Top 0.254: A03.P2 8.26,168.91 12.7,168.91 13.34,169.54 19.68,169.54 20.32,168.91 D03.P2
BMB08L  (via drill 0.61)
  Top 0.254: 9.53,173.99 12.7,173.99 15.24,171.45 16.51,172.72 19.05,172.72 20.32,173.99 D03.M2 | 9.53,173.99 8.26,173.99 A03.M2 | v19.68,75.56 17.14,75.56 v15.88,74.3 | v3.81,83.19 1.27,85.72 1.27,165.74 9.53,173.99
  Bottom 0.254: v19.68,75.56 31.75,63.5 31.75,62.23 39.37,54.61 41.27,56.52 41.27,57.78 39.37,59.69 41.27,61.59 43.81,61.59 64.77,40.64 64.77,38.73 D27.K1 | v15.88,74.3 12.7,74.3 v3.81,83.19
BMB09  (via drill 0.61)
  Top 0.254: v18.41,64.14 v62.23,107.95 | v16.51,155.57 20.32,159.38 20.32,161.29 D03.S2
  Bottom 0.254: v18.41,64.14 14.61,64.14 C20.A1 | v62.23,107.95 38.1,132.08 38.1,133.99 v16.51,155.57 12.06,160.02 9.53,160.02 8.26,161.29 A03.S2
BMB10
  Top 0.254: D03.T2 17.14,158.12 12.7,158.12 8.89,154.31 6.99,154.31 3.81,157.48 4.45,158.12 A03.T2
  Bottom 0.254: C20.F1 10.79,48.26 10.79,50.8 5.71,55.88 5.71,57.15 3.17,59.69 3.17,82.55 2.54,83.19 2.54,111.76 1.91,112.39 1.91,155.57 4.45,158.12 A03.T2
BMB11  (via drill 0.61)
  Top 0.254: v73.66,93.98 14.61,34.92 14.61,32.38 C20.M1 | A03.V2 5.08,151.76 10.79,146.05 17.14,152.4 D03.V2
  Bottom 0.254: v73.66,93.98 73.66,95.25 17.14,151.76 D03.V2
BRD_L  (via drill 0.61)
  Top 0.254: v69.85,78.74 49.53,58.42 45.09,58.42 29.21,42.55 27.94,42.55 11.43,26.04 8.26,26.04 C20.P2 | v63.5,94.61 63.5,96.52 67.94,100.97 67.94,104.78 v76.83,113.67 | v57.15,137.16 52.07,137.16 43.81,128.91 41.27,128.91 40.01,127.64 C22.C1
  Bottom 0.254: v69.85,78.74 69.85,88.27 v63.5,94.61 | v76.83,113.67 76.83,117.47 v57.15,137.16
BRUN  (via drill 0.61)
  Top 0.254: v12.7,87 19.05,87 20.32,88.27 D04.S2
  Bottom 0.254: v12.7,87 11.43,88.27 8.26,88.27 A04.S2
BSKIP  (via drill 0.61)
  Top 0.254: A04.K2 8.26,107.31 8.26,105.41 10.16,103.5 13.97,103.5 16.51,106.05 19.05,106.05 20.32,107.31 D04.K2 | v26.67,92.71 29.84,92.71 C22.R2
  Bottom 0.254: v26.67,92.71 16.51,102.87 15.24,102.87 12.06,106.05 9.53,106.05 8.26,107.31 A04.K2
BTS1
  Top 0.254: A02.T2 5.08,227.97 5.08,226.06 8.89,222.25 13.34,226.69 15.88,226.69 17.14,227.97 D02.T2
BTS3
  Bottom 0.254: A02.S2 8.26,232.41 12.7,232.41 15.24,234.95 16.51,233.68 19.05,233.68 20.32,232.41 D02.S2
BWR_L  (via drill 0.61)
  Top 0.254: D21.C1 52.07,269.24 49.53,269.24 44.45,264.16 44.45,262.25 43.18,260.99 D21.F2 | D21.M2 46.35,245.11 46.35,248.92 47.62,250.19 47.62,252.09 48.9,253.37 D21.J1 | v2.54,59.05 2.54,79.38 10.16,87 10.16,88.27 58.42,136.53 58.42,153.03 66.67,161.29 66.67,165.1 v78.74,177.16 | D21.P1 52.07,237.49 49.53,237.49 44.45,232.41 44.45,230.5 43.18,229.24 D21.T2
  Bottom 0.254: D21.P1 52.07,238.76 49.53,238.76 47.62,240.66 47.62,242.57 46.35,243.84 D21.M2 | D21.F2 43.18,259.71 45.72,259.71 47.62,257.81 47.62,255.91 48.9,254.63 D21.J1 | v2.54,59.05 1.91,58.42 1.91,54.61 2.54,53.98 2.54,44.45 4.45,42.55 4.45,41.91 C20.J2 | v78.74,177.16 78.74,190.5 44.45,224.79 44.45,226.69 43.18,227.97 D21.T2
C0L  (via drill 0.61)
  Top 0.254: 27.3,15.24 25.4,15.24 24.77,14.61 9.53,14.61 1.27,22.86 25.4,46.99 25.4,48.9 26.67,50.16 C21.E1 | 27.3,15.24 29.84,15.24 D22.T2 | v74.93,109.22 74.93,101.6 v64.77,91.44 | v73.03,65.41 73.03,60.96 27.3,15.24
  Bottom 0.254: C21.D1 24.13,53.34 24.77,53.34 26.67,51.44 C21.E1 | v74.93,109.22 65.41,118.75 65.41,120.02 C27.E1 | v64.77,91.44 66.67,89.53 66.67,85.72 68.58,83.82 68.58,69.85 v73.03,65.41
C1L
  Top 0.254: C21.A1 26.67,62.87 24.77,60.96 24.13,60.96 C21.B1 23.5,60.96 20.32,60.96 17.14,64.14 | 17.14,64.14 8.89,55.88 6.35,55.88 5.08,54.61 C20.D2 | 17.14,64.14 64.77,111.76 64.77,113.67 C27.H1
  Bottom 0.254: C20.D2 4.45,53.34 4.45,48.26 C20.F2 5.08,46.99 6.35,45.72 6.35,43.81 33.02,17.14 33.02,13.34 D22.U2
C20U1
  Top 0.254: C20.H1 13.97,43.81 13.34,43.81 11.43,41.91 C20.J1 10.79,40.64 8.26,40.64 6.35,38.73 6.35,36.83 5.08,35.56 C20.L2 4.45,34.29 4.45,29.21 C20.N2 | C20.C1 13.97,56.52 13.34,56.52 11.43,54.61 C20.D1 10.79,53.34 8.89,51.44 8.26,51.44 C20.E2 7.62,50.16 7.62,45.09 C20.H2 | C20.R1 11.43,22.86 12.06,22.86 13.97,24.77 C20.P1
  Bottom 0.254: C20.H2 8.26,43.81 8.89,43.81 10.79,41.91 C20.J1 11.43,40.64 13.34,38.73 13.97,38.73 C20.K1 | C20.B1 11.43,59.69 12.06,59.69 13.97,57.78 C20.C1 | C20.U1 13.97,13.34 13.97,17.14 12.7,18.41 12.7,20.32 11.43,21.59 C20.R1 | C20.P1 13.97,26.04 12.06,27.94 11.43,27.94 C20.N1 10.79,27.94 5.08,27.94 C20.N2
C21U1  (via drill 0.61)
  Top 0.254: v76.2,59.69 29.84,13.34 27.3,13.34 C21.U1 | v69.85,93.34 69.85,93.98 76.2,100.33 76.2,107.95 v80.01,111.76 | v74.3,179.07 74.3,250.19 48.26,276.23 43.81,271.78 41.27,271.78 40.01,270.51 D20.C1
  Bottom 0.254: v76.2,59.69 76.2,87 v69.85,93.34 | v80.01,111.76 81.28,113.03 81.28,172.09 v74.3,179.07
C32H2  (via drill 0.61)
  Top 0.254: v44.45,67.94 44.45,69.85 v53.34,78.74 | v31.75,99.69 31.75,102.23 41.91,112.39 44.45,112.39 45.72,113.67 C32.H2
  Bottom 0.254: v44.45,67.94 52.07,60.33 52.07,57.78 D31.C1 | v53.34,78.74 36.83,95.25 36.2,95.25 v31.75,99.69
DATA00LL  (via drill 0.61)
  Top 0.254: v57.15,83.82 30.48,57.15 30.48,54.61 D22.D2 | v33.02,123.83 33.02,124.46 38.1,129.54 38.1,131.44 39.37,132.72 C22.A1 39.37,133.99 42.55,137.16 27.3,152.4 27.3,153.03 67.94,193.68 v67.94,226.06
  Bottom 0.254: D21.D1 48.9,267.33 47.62,268.61 45.09,268.61 43.81,269.88 41.27,267.33 41.27,259.71 61.59,239.4 61.59,235.59 A27.R1 62.23,234.31 62.23,231.78 v67.94,226.06 | v57.15,83.82 57.15,86.36 40.64,102.87 36.2,102.87 34.92,104.14 34.92,105.41 36.2,106.68 41.27,106.68 45.72,111.12 v33.02,123.83
DATA01L  (via drill 0.61)
  Top 0.254: v28.57,53.34 28.57,56.52 v66.67,94.61 68.58,96.52 68.58,97.79 72.39,101.6 72.39,107.95 81.28,116.84 81.28,141.6 v74.3,148.59 | v36.83,186.69 63.5,213.36 63.5,226.06 64.77,227.33 64.77,231.14 A27.S1
  Bottom 0.254: A27.S1 65.41,232.41 67.31,232.41 74.3,239.4 53.98,259.71 53.98,261.62 52.7,262.89 D21.E1 | v28.57,53.34 30.48,51.44 33.02,51.44 D22.E2 | v66.67,94.61 66.67,95.89 40.64,121.92 38.1,121.92 36.83,123.19 C22.D1 | v36.83,186.69 36.83,186.06 v74.3,148.59
DATA02L  (via drill 0.61)
  Top 0.254: A27.U1 65.41,226.06 65.41,229.87 66.67,231.14 66.67,238.76 53.34,252.09 52.7,251.46 D21.K1 | v38.1,57.15 38.1,53.34 33.02,48.26 30.48,48.26 D22.F2 | v36.83,68.58 36.83,73.66 v41.27,78.11 | v27.94,97.16 27.94,100.33 28.57,100.97 28.57,105.41 v38.1,114.94 | v69.85,207.65 69.85,177.16 50.16,157.48 50.16,155.57 47.62,153.03 47.62,137.79 38.1,128.27 38.1,123.19 37.47,122.56 36.83,122.56 v34.92,120.65
  Bottom 0.254: v38.1,57.15 38.1,67.31 v36.83,68.58 | v41.27,78.11 41.27,83.82 v27.94,97.16 | v38.1,114.94 38.1,115.57 36.83,116.84 C22.F1 36.2,118.11 34.92,119.38 v34.92,120.65 | v69.85,207.65 65.41,212.09 65.41,224.79 A27.U1
DATA03L  (via drill 0.61)
  Top 0.254: v76.83,98.42 v29.21,50.8 | v66.67,113.67 66.67,117.47 78.11,128.91 78.11,136.53 80.64,139.06 74.3,145.41 73.03,144.15 | 73.03,144.15 41.91,113.03 38.1,113.03 36.83,111.76 C22.J1 | v40.64,196.85 61.59,217.81 61.59,221.62 A27.V1 | v80.01,155.57 73.03,148.59 73.03,144.15
  Bottom 0.254: A27.V1 61.59,222.88 61.59,225.43 45.72,241.3 45.72,242.57 44.45,243.84 44.45,245.11 48.26,248.92 48.9,248.28 D21.L1 | v29.21,50.8 33.02,46.99 33.02,45.09 D22.H2 | v76.83,98.42 76.83,103.5 v66.67,113.67 | v40.64,196.85 40.64,196.22 45.09,191.77 45.09,190.5 v80.01,155.57
DATA04L  (via drill 0.61)
  Top 0.254: v71.12,202.56 71.12,172.09 66.04,167 63.5,167 62.23,165.74 B27.R1 | v45.72,36.2 46.35,36.2 53.98,43.81 53.98,48.9 v63.5,58.42 | v67.94,156.21 67.94,146.05 v60.96,139.06 | v68.58,127 47.62,106.05 v47.62,102.23
  Bottom 0.254: v71.12,202.56 64.14,209.55 64.14,217.81 50.8,231.14 50.8,232.41 49.53,233.68 49.53,234.31 D21.R1 | v45.72,36.2 42.55,39.37 34.92,39.37 33.66,40.64 30.48,40.64 D22.J2 | v63.5,58.42 63.5,81.28 47.62,97.16 | 47.62,97.16 41.27,103.5 37.47,103.5 36.83,104.14 C22.L1 | v67.94,156.21 62.23,161.93 62.23,164.47 B27.R1 | v60.96,139.06 60.96,134.62 v68.58,127 | v47.62,102.23 47.62,97.16
DATA05L  (via drill 0.61)
  Top 0.254: v44.45,50.8 44.45,46.99 36.2,38.73 33.66,38.73 D22.K2 | v58.42,73.66 v44.45,59.69 | v25.4,203.84 26.67,205.1 27.94,205.1 52.07,229.24 52.07,231.14 D21.S1 | v60.33,83.19 60.33,86.36 64.14,90.17 64.77,90.17 75.56,100.97 75.56,108.58 v80.01,113.03
  Bottom 0.254: v44.45,59.69 v44.45,50.8 | v58.42,73.66 58.42,78.74 57.78,79.38 | 57.78,79.38 40.64,96.52 38.1,96.52 36.83,97.79 C22.N1 | v25.4,203.84 25.4,199.39 35.56,189.23 40.01,189.23 63.5,165.74 63.5,163.83 64.77,162.56 B27.S1 65.41,161.29 78.11,148.59 78.11,139.06 80.64,136.53 80.64,125.09 80.01,124.46 v80.01,113.03 | 57.78,79.38 60.96,82.55 v60.33,83.19
DATA06L  (via drill 0.61)
  Top 0.254: v60.33,67.94 30.48,38.1 30.48,35.56 D22.L2 | v79.38,125.09 79.38,118.11 v45.72,84.45 | v38.1,182.88 66.67,211.46 66.67,226.06 73.66,233.04 73.66,240.66 64.77,249.56 64.14,248.92 60.96,248.92 59.69,247.65 50.8,256.54 46.35,256.54 D21.H2
  Bottom 0.254: v60.33,67.94 60.33,70.48 45.72,85.09 | 45.72,85.09 40.64,90.17 38.1,90.17 36.83,91.44 C22.R1 | 65.41,153.03 65.41,149.86 78.11,137.16 78.11,135.25 78.74,134.62 78.74,128.27 79.38,127.64 v79.38,125.09 | 65.41,153.03 65.41,154.94 B27.U1 | v45.72,84.45 45.72,85.09 | v38.1,182.88 38.1,180.34 65.41,153.03
DATA07L  (via drill 0.61)
  Top 0.254: v57.15,53.34 36.2,32.38 33.66,32.38 D22.M2 | v80.01,212.72 80.01,175.9 78.74,174.62 78.74,171.45 63.5,156.21 63.5,154.31 62.23,153.03 B27.V1 | v59.05,70.48 80.64,92.08 80.64,93.34 81.28,93.98 81.28,107.95 v80.01,109.22 | v70.48,118.75 70.48,120.02 v78.11,127.64
  Bottom 0.254: v57.15,53.34 57.15,56.52 50.8,62.87 50.8,64.77 | 50.8,64.77 36.83,78.74 C22.V1 | v80.01,212.72 50.8,241.94 50.8,248.28 45.72,253.37 43.18,253.37 D21.J2 | 50.8,64.77 57.78,71.75 v59.05,70.48 | v70.48,118.75 v80.01,109.22 | v78.11,127.64 78.11,133.99 77.47,134.62 77.47,136.53 62.23,151.76 B27.V1
DATA08L  (via drill 0.61)
  Top 0.254: v36.83,126.36 33.66,123.19 33.66,121.28 C22.E2 | v3.17,203.84 38.73,239.4 41.27,239.4 42.55,240.66 D21.N2 | v11.43,55.88 10.16,55.88 9.53,55.24 8.26,55.24 5.71,52.7 3.81,52.7 1.27,55.24 1.27,79.38 5.08,83.19 1.91,86.36 1.91,112.39 v28.57,139.06
  Bottom 0.254: D27.R1 61.59,22.86 60.33,24.13 57.78,24.13 54.61,27.3 35.56,27.3 34.92,27.94 30.48,27.94 D22.N2 29.84,29.21 29.84,33.02 12.7,50.16 12.7,54.61 v11.43,55.88 | v36.83,126.36 36.83,127.64 31.75,132.72 31.75,135.89 v28.57,139.06 6.35,161.29 6.35,179.07 5.71,179.71 5.71,180.97 3.17,183.51 v3.17,203.84
DATA09L  (via drill 0.61)
  Top 0.254: 31.11,114.94 29.21,114.94 26.67,117.47 v30.48,121.28 | 31.11,114.94 33.02,114.94 C22.H2 | v22.23,142.88 22.23,153.03 29.21,160.02 29.21,161.93 34.92,167.64 34.92,178.44 v63.5,207.01 | v5.71,90.17 v5.71,87.63 | v6.35,102.23 6.99,102.87 18.41,102.87 26.04,110.49 26.67,110.49 31.11,114.94
  Bottom 0.254: D27.S1 64.77,19.68 63.5,20.95 60.96,20.95 58.42,23.5 57.15,23.5 56.52,24.13 38.73,24.13 38.1,24.77 33.66,24.77 D22.P2 33.02,26.04 30.48,26.04 28.57,27.94 28.57,33.02 12.06,49.53 12.06,50.8 6.35,56.52 6.35,69.22 11.43,74.3 12.06,73.66 15.24,73.66 15.88,73.03 17.14,74.3 15.88,75.56 12.7,75.56 6.35,81.92 6.35,87 v5.71,87.63 | v30.48,121.28 25.4,126.36 25.4,139.7 v22.23,142.88 | v63.5,207.01 63.5,217.17 50.16,230.5 50.16,231.78 47.62,234.31 47.62,236.22 46.35,237.49 D21.P2 | v5.71,90.17 8.26,92.71 6.35,94.61 v6.35,102.23
DATA10L  (via drill 0.61)
  Top 0.254: v11.43,71.12 29.21,88.9 25.4,92.71 26.67,93.98 27.94,93.98 28.57,94.61 28.57,95.25 29.84,96.52 28.57,97.79 28.57,99.06 31.11,101.6 31.11,102.87 33.02,104.78 33.02,107.31 C22.K2 | v15.88,57.78 15.88,48.26 v12.7,45.09 10.79,43.18 v2.54,43.18 | v1.91,196.22 29.84,224.16 40.64,224.16 41.27,224.79 45.72,224.79 D21.U2
  Bottom 0.254: 33.02,21.59 34.92,21.59 35.56,20.95 54.61,20.95 60.96,14.61 63.5,14.61 64.77,13.34 D27.U1 | 33.02,21.59 30.48,21.59 D22.R2 | v11.43,71.12 11.43,62.23 v15.88,57.78 | v12.7,45.09 12.7,41.91 33.02,21.59 | v1.91,196.22 1.91,156.84 1.27,156.21 1.27,44.45 v2.54,43.18
DATA11L  (via drill 0.61)
  Top 0.254: 33.02,99.06 33.02,97.16 31.75,95.89 31.75,89.53 22.23,80.01 22.23,76.83 16.51,71.12 16.51,67.94 v3.17,54.61 | 33.02,99.06 33.02,100.97 C22.M2 | v80.64,173.99 80.64,163.83 79.38,162.56 79.38,156.21 41.27,118.11 v41.27,114.3 | v41.27,107.95 41.27,107.31 33.02,99.06
  Bottom 0.254: 43.18,11.43 37.47,17.14 34.92,17.14 33.66,18.41 D22.S2 | 43.18,11.43 51.44,3.17 57.15,8.89 61.59,8.89 D27.V1 | v3.17,54.61 3.17,45.09 12.7,35.56 12.7,31.11 32.38,11.43 43.18,11.43 | v80.64,173.99 43.18,211.46 43.18,221.62 D21.V2 | v41.27,114.3 v41.27,107.95
GND  (via drill 0.61)
  Top 0.254: D32.U2 71.75,13.34 72.39,13.34 74.3,15.24 D32.T1 74.3,16.51 74.3,21.59 D32.R1 74.3,22.86 74.3,27.94 | 67.94,27.94 66.67,26.67 64.14,26.67 53.98,16.51 49.53,16.51 D31.T1 | 67.94,27.94 67.94,22.86 D32.R2 | D32.N2 67.94,27.94 | 74.3,27.94 68.58,27.94 D32.N2 | 74.3,27.94 D32.N1 | D32.A1 77.47,62.87 77.47,57.78 D32.C1 77.47,56.52 77.47,52.7 71.75,46.99 | 22.23,17.14 22.86,17.14 23.5,16.51 C21.T1 | 22.23,17.14 16.51,17.14 15.88,16.51 11.43,16.51 C20.T1 | D32.J2 67.94,40.64 67.94,35.56 D32.L2 67.94,34.29 67.94,29.21 D32.N2 | 71.75,46.99 68.58,46.99 D32.F2 | 71.75,46.99 74.3,46.99 D32.F1 | 33.66,42.55 v33.02,42.55 | 33.66,42.55 44.45,53.34 44.45,55.24 45.72,56.52 D31.C2 | 22.23,17.14 22.23,31.11 33.66,42.55 | A02.U2 8.26,226.06 8.89,226.06 10.79,227.97 A02.T1 10.79,229.24 10.79,234.31 A02.R1 11.43,234.31 17.14,234.31 D02.R2 17.78,234.31 23.5,234.31 | D21.V1 49.53,222.88 50.16,222.88 52.07,224.79 D21.U1 | D02.U2 20.95,226.06 21.59,226.06 23.5,227.97 D02.T1 23.5,229.24 23.5,234.31 | D02.N1 23.5,240.66 23.5,235.59 D02.R1 23.5,234.31 | A02.C2 8.26,269.24 13.97,269.24 A02.C1 | A02.C1 14.61,269.24 20.32,269.24 D02.C2 20.95,269.24 26.67,269.24 D02.C1 | A02.A1 13.97,275.59 13.97,270.51 A02.C1 | D02.C1 26.67,270.51 26.67,275.59 D02.A1 | D20.C2 33.02,269.24 27.3,269.24 D02.C1 | A02.R2 4.45,235.59 4.45,240.66 A02.N2 | A02.N2 4.45,241.94 4.45,247.01 A02.L2 4.45,248.28 4.45,253.37 A02.J2 4.45,254.63 4.45,259.71 A02.F2 5.08,259.71 10.79,259.71 A02.F1 11.43,259.71 17.14,259.71 D02.F2 | 17.14,245.11 17.14,247.01 D02.L2 | 17.14,245.11 17.14,241.94 D02.N2 | A02.K1 14.61,251.46 16.51,253.37 17.14,253.37 D02.J2 17.78,254.63 19.05,255.91 21.59,255.91 23.5,257.81 23.5,259.71 D02.F1
  Top 0.254: 17.14,245.11 22.23,250.19 26.67,250.19 D02.K1 | A02.N1 10.79,240.66 5.08,240.66 A02.N2 | 9.53,199.39 13.97,199.39 A03.C1 | 9.53,199.39 8.26,199.39 A03.C2 | D03.C2 20.32,199.39 14.61,199.39 A03.C1 | A03.A1 13.97,205.74 13.97,200.66 A03.C1 | A03.N2 4.45,172.09 4.45,177.16 A03.L2 4.45,178.44 4.45,183.51 A03.J2 4.45,184.78 4.45,189.87 A03.F2 5.08,189.87 9.53,189.87 | 9.53,189.87 10.79,189.87 A03.F1 11.43,189.87 17.14,189.87 | 9.53,199.39 9.53,189.87 | D03.U2 20.95,156.21 21.59,156.21 23.5,158.12 D03.T1 | C31.T1 48.9,158.12 44.45,158.12 43.81,157.48 37.47,157.48 36.83,158.12 C30.T1 | C30.C2 33.02,199.39 27.3,199.39 D03.C1 26.67,199.39 26.67,195.58 20.95,189.87 | A03.U2 8.26,156.21 8.89,156.21 10.79,158.12 A03.T1 10.79,159.38 10.79,164.47 A03.R1 | A03.K1 14.61,181.61 16.51,183.51 17.14,183.51 D03.J2 17.14,184.78 17.14,189.87 | 20.95,189.87 17.78,189.87 D03.F2 17.14,189.87 | 20.95,189.87 23.5,189.87 D03.F1 | D03.K1 26.67,180.34 22.23,180.34 21.59,179.71 19.05,179.71 17.78,178.44 D03.L2 | A03.N1 11.43,170.81 17.14,170.81 D03.N2 17.78,170.81 23.5,170.81 D03.N1 | A04.U2 8.26,83.19 8.89,83.19 10.79,85.09 A04.T1 11.43,86.36 11.43,88.27 13.34,90.17 15.88,90.17 17.14,91.44 D04.R2 17.78,91.44 23.5,91.44 D04.R1 | A04.C2 8.26,126.36 13.97,126.36 A04.C1 13.97,127.64 13.97,132.72 A04.A1 | 25.4,126.36 26.67,126.36 D04.C1 | 25.4,126.36 20.95,126.36 D04.C2 | C22.C2 33.02,126.36 32.38,126.36 30.48,124.46 C22.D2 | v41.27,125.09 44.45,128.27 45.09,127.64 45.72,127.64 C32.C2 | D04.U2 20.95,83.19 21.59,83.19 23.5,85.09 D04.T1 | v33.66,84.45 34.29,85.09 36.2,85.09 C22.T1 | A04.N1 10.79,97.79 10.79,92.71 A04.R1 10.79,91.44 5.08,91.44 A04.R2 4.45,92.71 4.45,97.79 A04.N2 4.45,99.06 4.45,104.14 A04.L2 4.45,105.41 4.45,110.49 A04.J2
  Top 0.254: A04.K1 14.61,108.58 15.24,108.58 17.14,110.49 D04.J2 17.14,111.76 17.14,116.84 | 17.14,116.84 11.43,116.84 A04.F1 | 17.14,116.84 D04.F2 17.78,116.84 23.5,116.84 D04.F1 24.13,118.11 25.4,119.38 25.4,126.36
  Bottom 0.254: D32.C2 71.75,56.52 77.47,56.52 D32.C1 | 19.68,55.88 13.34,55.88 12.06,57.15 C20.C2 | 19.68,55.88 20.32,56.52 C21.C2 | 49.53,51.44 64.14,36.83 66.67,36.83 67.94,35.56 D32.L2 | 49.53,51.44 46.35,54.61 46.35,56.52 D31.C2 | 67.94,43.81 67.94,41.91 D32.J2 | 67.94,43.81 67.94,46.99 D32.F2 | 67.94,43.81 73.03,38.73 77.47,38.73 D32.K1 | v33.02,42.55 19.68,55.88 | A02.N1 10.79,240.66 10.79,235.59 A02.R1 | D21.U1 52.07,226.06 50.16,227.97 49.53,227.97 D21.T1 48.9,229.24 44.45,229.24 43.81,229.87 36.2,229.87 | 36.2,229.87 36.2,231.14 27.94,239.4 25.4,239.4 24.13,240.66 D02.N1 | 36.2,229.87 36.2,229.24 D20.T1 | D21.C2 45.72,270.51 41.27,270.51 40.64,271.14 34.29,271.14 33.66,270.51 D20.C2 | A02.K1 14.61,250.19 15.24,250.19 17.14,248.28 D02.L2 | D02.F2 17.14,259.71 17.14,254.63 D02.J2 | A02.C2 8.26,269.24 8.26,265.43 9.53,264.16 9.53,262.25 10.79,260.99 A02.F1 | A03.R2 4.45,165.74 4.45,170.81 A03.N2 | D03.T1 23.5,159.38 23.5,164.47 D03.R1 23.5,165.74 23.5,167.64 | 23.5,167.64 23.5,170.81 D03.N1 | 23.5,167.64 31.75,159.38 36.2,159.38 C30.T1 | 26.67,201.29 26.67,205.74 D03.A1 | 26.67,201.29 26.67,200.66 D03.C1 | 26.67,201.29 40.64,201.29 41.27,200.66 45.72,200.66 C31.C2 | A03.N1 10.79,170.81 10.79,165.74 A03.R1 | D03.R2 17.14,165.74 17.14,170.81 D03.N2 17.14,172.09 17.14,177.16 D03.L2 17.14,178.44 15.24,180.34 14.61,180.34 A03.K1 | 33.02,59.69 33.02,57.78 D22.C2 | 33.02,59.69 12.06,80.64 9.53,80.64 8.26,81.92 A04.U2 | C22.D2 29.84,124.46 29.21,124.46 27.3,126.36 D04.C1 26.67,127.64 26.67,132.72 D04.A1 | v41.27,125.09 34.92,125.09 33.66,126.36 C22.C2 | A04.C1 14.61,127.64 20.32,127.64 D04.C2
  Bottom 0.254: 17.14,97.16 17.14,97.79 D04.N2 | 17.14,97.16 17.14,92.71 D04.R2 | D04.T1 23.5,86.36 23.5,91.44 D04.R1 24.13,91.44 25.4,90.17 27.94,90.17 v33.66,84.45 | A04.J2 4.45,111.76 4.45,116.84 A04.F2 5.08,116.84 10.79,116.84 A04.F1 | A04.K1 13.97,107.31 15.88,105.41 17.14,105.41 D04.L2 17.78,104.14 19.05,102.87 21.59,102.87 22.23,102.23 22.23,100.97 23.5,99.69 23.5,99.06 D04.N1 | D04.K1 26.67,108.58 26.67,110.49 24.77,112.39 24.77,116.2 24.13,116.84 D04.F1 | 17.14,97.16 12.06,97.16 11.43,97.79 A04.N1 | A03.U2 8.26,154.94 8.26,139.7 13.97,133.99 A04.A1 | A02.U2 8.26,224.79 8.26,212.72 13.97,207.01 A03.A1 | 49.53,51.44 45.72,47.62 39.37,53.98 38.73,53.98 33.02,59.69
IRQL
  Top 0.254: C22.S2 33.66,89.53 33.66,93.34 41.27,100.97 41.27,102.87 42.55,104.14 C32.L2
  Bottom 0.254: C27.P1 64.77,95.89 60.96,95.89 47.62,109.22 45.09,109.22 41.91,106.05 42.55,105.41 C32.L2
MD09L  (via drill 0.61)
  Top 0.254: v50.16,30.48 55.24,30.48 57.78,33.02 60.33,33.02 61.59,34.29 D27.L1
  Bottom 0.254: v50.16,30.48 43.81,36.83 32.38,36.83 29.21,40.01 27.94,40.01 17.78,50.16 14.61,50.16 C20.E1
MD10L  (via drill 0.61)
  Top 0.254: v31.11,11.43 42.55,11.43 60.96,29.84 63.5,29.84 64.77,31.11 D27.M1
  Bottom 0.254: v31.11,11.43 11.43,31.11 11.43,34.29 C20.L1
MD11L  (via drill 0.61)
  Top 0.254: v29.84,7.62 49.53,7.62 63.5,21.59 63.5,23.5 64.77,24.77 D27.P1
  Bottom 0.254: v29.84,7.62 19.05,18.41 14.61,18.41 C20.S1
N$1
  Top 0.254: D20.B1 36.83,273.69 41.27,273.69 45.09,277.5 51.44,277.5 52.07,276.86 D21.A1
N$2
  Top 0.254: D20.E1 40.01,264.16 42.55,264.16 47.62,269.24 47.62,271.14 48.9,272.42 D21.B1
N$3
  Top 0.254: D20.H1 39.37,256.54 39.37,252.73 38.1,251.46 38.1,249.56 39.37,248.28 41.27,250.19 41.27,254.63 45.09,258.44 47.62,258.44 48.9,259.71 D21.F1
N$4
  Top 0.254: D20.K1 40.01,251.46 40.01,254.63 44.45,259.08 45.72,259.08 48.26,261.62 50.16,261.62 53.34,258.44 52.7,257.81 D21.H1
N$5
  Top 0.254: D20.P1 40.01,238.76 44.45,238.76 45.09,239.4 47.62,239.4 48.9,240.66 D21.N1
N$6
  Top 0.254: D20.M1 40.01,243.84 44.45,243.84 46.99,241.3 48.26,242.57 50.8,242.57 52.07,243.84 D21.M1
N$7
  Top 0.254: 7.62,35.56 7.62,37.47 C20.K2 | 7.62,35.56 7.62,32.38 C20.M2 | 7.62,35.56 26.67,54.61 26.67,56.52 C21.C1
N$8
  Bottom 0.254: D20.N2 30.48,240.66 30.48,238.76 35.56,233.68 44.45,233.68 45.72,232.41 D21.S2
N$9  (via drill 0.61)
  Top 0.254: v44.45,127 43.18,125.73 43.18,124.46 C32.D2 | v80.01,93.98 80.01,92.71 57.78,70.48 57.78,69.22 52.7,64.14 D31.A1
  Bottom 0.254: D31.A1 52.7,62.87 57.15,62.87 64.14,55.88 66.67,55.88 67.94,54.61 D32.D2 | v44.45,127 44.45,128.27 45.72,129.54 59.69,115.57 60.96,115.57 71.12,105.41 71.12,102.87 v80.01,93.98
N$10
  Bottom 0.254: D20.J2 30.48,253.37 34.92,253.37 38.73,249.56 41.27,249.56 42.55,248.28 D21.L2
N$11  (via drill 0.61)
  Top 0.254: v60.33,243.84 42.55,226.06 40.01,226.06 D20.U1
  Bottom 0.254: v60.33,243.84 60.33,251.46 50.16,261.62 47.62,261.62 46.35,262.89 D21.E2
N$12  (via drill 0.61)
  Top 0.254: v57.15,247.01 42.55,232.41 40.01,232.41 D20.S1
  Bottom 0.254: v57.15,247.01 57.15,250.19 44.45,262.89 44.45,264.8 43.18,266.06 D21.D2
N$13
  Bottom 0.254: D20.F2 30.48,259.71 34.92,259.71 41.91,252.73 44.45,252.73 45.72,251.46 D21.K2
N$14
  Bottom 0.254: D20.L2 30.48,247.01 33.02,247.01 41.27,238.76 41.27,236.85 42.55,235.59 D21.R2
N$15  (via drill 0.61)
  Top 0.254: D31.D1 49.53,54.61 52.7,54.61 v56.52,58.42 78.11,80.01 v78.11,87.63 | v48.9,115.57 49.53,115.57 v55.88,121.92 | v73.66,107.95 73.66,101.6 v69.85,97.79
  Bottom 0.254: v56.52,58.42 60.33,58.42 63.5,55.24 64.77,55.24 67.31,52.7 69.85,52.7 71.12,51.44 D32.E2 | v48.9,115.57 46.35,118.11 46.35,120.02 C32.E2 | v55.88,121.92 59.69,121.92 v73.66,107.95 | v69.85,97.79 69.85,95.89 v78.11,87.63
N$16  (via drill 0.61)
  Top 0.254: v59.69,40.01 64.77,40.01 67.31,42.55 69.85,42.55 71.12,43.81 D32.H2 | v52.7,125.09 45.72,118.11 43.18,118.11 C32.F2 | v78.11,104.78 78.11,97.16 v65.41,84.45
  Bottom 0.254: v59.69,40.01 52.7,46.99 49.53,46.99 D31.F1 | v52.7,125.09 57.78,125.09 v78.11,104.78 | v65.41,84.45 66.67,83.19 66.67,57.78 73.03,51.44 73.03,46.35 71.75,45.09 D32.H2
N$17  (via drill 0.61)
  Top 0.254: v50.8,87.63 50.8,83.19 v38.1,70.48
  Bottom 0.254: 71.12,35.56 72.39,36.83 71.75,37.47 D32.K2 | 71.12,35.56 66.04,30.48 51.44,30.48 49.53,32.38 49.53,34.29 D31.L1 | v50.8,87.63 43.18,95.25 43.18,97.79 C32.N2 | v38.1,70.48 38.1,68.58 71.12,35.56
N$18  (via drill 0.61)
  Top 0.254: v17.78,70.48 17.78,71.12 v75.56,128.91 | 41.27,173.99 41.27,182.25 42.55,183.51 C31.J2 | v41.27,169.54 41.27,173.99 | 41.27,173.99 48.9,181.61 48.9,183.51 C31.J1 49.53,184.78 50.16,185.42 v50.16,187.32
  Bottom 0.254: v17.78,70.48 49.53,38.73 52.07,38.73 D31.K1 | v75.56,128.91 75.56,135.25 v41.27,169.54 | v50.16,187.32 46.35,191.13 46.35,193.04 C31.E2
N$19
  Bottom 0.254: C21.F1 23.5,48.26 22.86,48.26 20.95,50.16 C21.E2
N$20  (via drill 0.61)
  Top 0.254: v27.94,41.27 27.3,40.64 27.3,38.73 C21.K1
  Bottom 0.254: v27.94,41.27 19.05,50.16 19.05,52.07 17.78,53.34 C21.D2
N$21
  Top 0.254: C31.D1 49.53,197.49 50.16,197.49 52.07,199.39 C31.C1
N$22
  Top 0.254: C31.D2 43.18,197.49 45.72,197.49 47.62,199.39 47.62,201.29 48.9,202.56 C31.B1
  Bottom 0.254: C31.F1 48.9,191.13 48.9,193.04 46.99,194.94 44.45,194.94 43.18,196.22 C31.D2
N$23  (via drill 0.61)
  Top 0.254: v39.37,77.47 28.57,66.67 28.57,62.87 17.78,52.07 17.78,48.26 C21.F2
  Bottom 0.254: v39.37,77.47 39.37,78.74 37.47,80.64 34.92,80.64 33.66,81.92 C22.U2
N$24  (via drill 0.61)
  Top 0.254: v31.75,167.64 31.75,183.51 38.1,189.87 38.1,191.77 39.37,193.04 C30.E1
  Bottom 0.254: v31.75,167.64 39.37,160.02 43.81,160.02 45.09,158.75 43.81,157.48 35.56,157.48 34.92,158.12 30.48,158.12 C30.T2
N$25
  Bottom 0.254: C30.F1 36.83,191.13 40.64,191.13 42.55,193.04 44.45,191.13 44.45,189.87 46.35,187.96 C31.H2
N$26
  Bottom 0.254: C31.L2 43.18,177.16 43.81,177.16 45.72,175.26 C31.M2 46.35,173.99 48.26,172.09 48.9,172.09 C31.N1
N$28
  Top 0.254: C31.N2 43.18,172.09 43.18,174.62 49.53,180.97 49.53,182.25 50.8,183.51 50.8,185.42 52.07,186.69 C31.H1
N$29  (via drill 0.61)
  Top 0.254: v61.59,194.31 52.7,185.42 52.7,181.61 C31.K1
  Bottom 0.254: v61.59,194.31 61.59,194.94 53.98,202.56 53.98,204.47 52.7,205.74 C31.A1
N$30
  Top 0.254: C31.K2 46.35,181.61 46.35,185.42 50.8,189.87 50.8,191.77 52.07,193.04 C31.E1
OPAUSEL  (via drill 0.61)
  Top 0.254: v79.38,139.06 64.77,124.46 62.23,124.46 C27.D1
  Bottom 0.254: v79.38,139.06 79.38,151.76 44.45,186.69 44.45,188.59 43.18,189.87 C31.F2
PAUSEL  (via drill 0.61)
  Top 0.254: C21.J1 24.13,41.91 24.77,41.91 26.67,43.81 C21.H1 | D31.H1 52.07,43.81 50.16,41.91 49.53,41.91 D31.J1 48.9,40.64 48.26,40.01 v45.72,40.01
  Bottom 0.254: v45.72,40.01 35.56,40.01 34.29,41.27 33.02,41.27 30.48,43.81 27.3,43.81 C21.H1
POWEROK  (via drill 0.61)
  Top 0.254: v69.85,134.62 47.62,112.39 47.62,107.31 46.35,106.05 46.35,102.23 C32.M2
  Bottom 0.254: v69.85,134.62 69.85,137.79 55.88,151.76 B27.V2
SKIPL
  Top 0.254: C22.P2 33.66,95.89 33.66,97.79 41.91,106.05 44.45,106.05 45.72,107.31 C32.K2
  Bottom 0.254: C27.S1 64.77,89.53 60.96,89.53 56.52,93.98 56.52,95.25 47.62,104.14 47.62,106.05 46.35,107.31 C32.K2
STROBE  (via drill 0.61)
  Top 0.254: v19.05,67.94 19.05,71.12 v59.69,111.76 | v28.57,153.03 49.53,173.99 52.07,173.99 C31.M1 | v59.69,116.84 59.69,115.57 59.05,114.94 C27.H2
  Bottom 0.254: C31.M1 52.07,175.26 51.44,175.26 49.53,177.16 C31.L1 | v19.05,67.94 52.07,34.92 52.07,32.38 D31.M1 | v59.69,111.76 59.69,113.03 59.05,113.67 C27.H2 | v28.57,153.03 28.57,146.69 43.81,131.44 45.09,131.44 v59.69,116.84
T2  (via drill 0.61)
  Top 0.254: v10.16,89.53 9.53,88.9 9.53,88.27 7.62,86.36 5.08,86.36 A04.T2
  Bottom 0.254: v10.16,89.53 11.43,89.53 13.34,87.63 15.88,87.63 17.14,86.36 D04.T2
TP3  (via drill 0.61)
  Top 0.254: v78.74,92.71 49.53,63.5 49.53,60.96 D31.B1 | v63.5,111.76 63.5,115.57 v76.83,128.91
  Bottom 0.254: v78.74,92.71 70.48,100.97 70.48,104.78 v63.5,111.76 | v76.83,128.91 76.83,133.99 76.2,134.62 76.2,135.89 60.33,151.76 60.33,156.84 37.47,179.71 37.47,180.97 34.92,183.51 34.92,185.42 33.66,186.69 C30.H2
TP4  (via drill 0.61)
  Top 0.254: v79.38,80.01 52.7,53.34 52.7,51.44 D31.E1
  Bottom 0.254: v79.38,80.01 79.38,85.09 57.15,107.31 57.15,109.22 55.88,110.49 C27.J2
V2
  Top 0.254: A04.V2 5.08,78.74 10.79,73.03 17.14,79.38 D04.V2
VCC  (via drill 0.61)
  Top 0.254: v28.57,67.94 24.77,67.94 20.95,64.14 C21.A2 | 34.92,133.99 38.1,133.99 v41.27,137.16 | 34.92,133.99 33.66,133.99 C22.A2 | 34.92,133.99 34.92,142.88 29.21,148.59 22.23,141.6 21.59,141.6 15.24,147.96 28.57,161.29 28.57,186.69 44.45,202.56 44.45,204.47 45.72,205.74 C31.A2 | v80.01,95.25 59.69,74.93 58.42,74.93 47.62,64.14 46.35,64.14 D31.A2
  Bottom 0.254: 33.66,67.31 33.66,64.14 D22.A2 | 33.66,67.31 38.1,71.75 45.72,64.14 D31.A2 | C20.A2 8.26,64.14 8.26,69.22 11.43,72.39 20.32,63.5 C21.A2 | 33.66,67.31 29.21,67.31 v28.57,67.94 | D21.A2 45.72,276.23 39.37,282.57 33.66,276.86 D20.A2 33.02,276.86 28.57,276.86 27.94,277.5 13.34,277.5 1.27,265.43 1.27,236.22 6.99,230.5 11.43,230.5 34.29,207.65 | v41.27,137.16 42.55,137.16 45.72,133.99 C32.A2 46.35,132.72 47.62,131.44 50.16,131.44 53.34,128.27 59.69,128.27 80.01,107.95 v80.01,95.25 | 34.29,207.65 39.37,212.72 45.72,206.38 C31.A2 | 34.29,207.65 33.66,207.01 C30.A2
